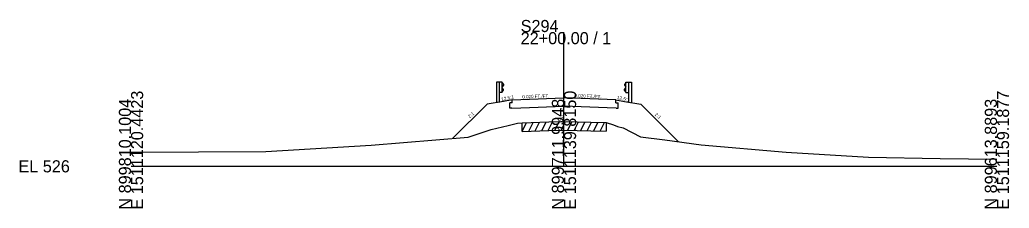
# Model space of a CAD drawing. Extents: x 974 to 2203, y -10 to 19041.
# Drawn here: x 1974.3 to 2202.8, y 3990.3 to 4033.9 of the extents above; entities that cross this region are included whole.
import ezdxf

# ---------------------------------------------------------------- set-up
doc = ezdxf.new("R2010")
doc.units = 0
for name, color, linetype in [('RD_GPK_XS_Cell', 7, 'Continuous'), ('RD_XS_Base', 7, 'Continuous'), ('RD_XS_EarthShd', 7, 'Continuous'), ('RD_XS_ExGround', 7, 'Continuous'), ('RD_XS_ExPaveRet', 7, 'Continuous'), ('RD_XS_GR', 7, 'Continuous'), ('RD_XS_Pave', 7, 'Continuous'), ('RD_XS_TX_Elev_EX', 7, 'Continuous'), ('RD_XS_TX_Slope', 7, 'Continuous')]:
    doc.layers.add(name, color=color, linetype=linetype)

msp = doc.modelspace()

# ---------------------------------------------------------------- linework, layer by layer
at = {"layer": 'RD_GPK_XS_Cell'}
for p, q in [((2100, 4000), (2100, 4031.03)), ((2000, 4000), (2100, 4000)), ((2100, 4000), (2200, 4000))]:
    msp.add_line(p, q, dxfattribs=at)
at = {"layer": 'RD_XS_Base'}
for p, q in [((2088, 4014.7), (2088, 4015.34)), ((2112, 4014.7), (2112, 4015.34)), ((2088, 4014.7), (2087.48, 4014.68)), ((2087.48, 4013.41), (2087.48, 4014.68)), ((2087.98, 4013.43), (2087.48, 4013.41)), ((2087.98, 4013.43), (2090, 4013.51)), ((2090, 4013.51), (2100, 4013.91)), ((2110, 4013.51), (2100, 4013.91)), ((2112.02, 4013.43), (2110, 4013.51)), ((2112, 4014.7), (2112.52, 4014.68)), ((2112.02, 4013.43), (2112.52, 4013.41)), ((2112.52, 4013.41), (2112.52, 4014.68))]:
    msp.add_line(p, q, dxfattribs=at)
at = {"layer": 'RD_XS_EarthShd'}
for p, q in [((2088, 4015.34), (2086, 4015.01)), ((2112, 4015.34), (2114, 4015.01)), ((2074.27, 4006.4), (2082.25, 4014.38)), ((2086, 4015.01), (2082.25, 4014.38)), ((2114, 4015.01), (2117.75, 4014.38)), ((2126.46, 4005.67), (2117.75, 4014.38))]:
    msp.add_line(p, q, dxfattribs=at)
at = {"layer": 'RD_XS_ExGround'}
msp.add_lwpolyline([(2000, 4003.3), (2031.15, 4003.45), (2055.5, 4004.85), (2077.88, 4006.7), (2083.15, 4008.5), (2087.14, 4009.46), (2089.3, 4009.95), (2090.36, 4010.07), (2096.51, 4010.28), (2099.9, 4010.34), (2106.23, 4010.19), (2109.73, 4010.1), (2111.47, 4009.56), (2112.39, 4009.21), (2113.68, 4008.93), (2117.7, 4006.82), (2123.3, 4006.12), (2131.66, 4004.93), (2151.35, 4003.25), (2170.37, 4002.08), (2186.86, 4001.84), (2200, 4001.63)], dxfattribs=at)
at = {"layer": 'RD_XS_ExPaveRet'}
for p, q in [((2090.36, 4008.07), (2091.38, 4010.11)), ((2090.36, 4008.07), (2090.36, 4010.07)), ((2091.86, 4008.12), (2092.88, 4010.16)), ((2093.36, 4008.17), (2094.38, 4010.21)), ((2094.86, 4008.22), (2095.88, 4010.26)), ((2096.36, 4008.27), (2097.37, 4010.3)), ((2097.86, 4008.31), (2098.87, 4010.33)), ((2099.36, 4008.33), (2100.36, 4010.33)), ((2100.86, 4008.32), (2101.85, 4010.3)), ((2102.36, 4008.29), (2103.35, 4010.26)), ((2103.86, 4008.25), (2104.85, 4010.23)), ((2105.36, 4008.21), (2106.35, 4010.19)), ((2106.86, 4008.18), (2107.85, 4010.15)), ((2108.36, 4008.14), (2109.35, 4010.11)), ((2109.73, 4010.1), (2109.73, 4008.1)), ((2090.36, 4008.07), (2096.51, 4008.28)), ((2096.51, 4008.28), (2099.9, 4008.34)), ((2099.9, 4008.34), (2106.23, 4008.19)), ((2106.23, 4008.19), (2109.73, 4008.1))]:
    msp.add_line(p, q, dxfattribs=at)
at = {"layer": 'RD_XS_GR'}
for p, q in [((2084.4, 4019.43), (2084.4, 4014.66)), ((2085.06, 4019.43), (2084.4, 4019.43)), ((2085.06, 4019.43), (2085.06, 4014.77)), ((2085.73, 4019.43), (2085.06, 4019.43)), ((2085.73, 4017.09), (2085.73, 4019.43)), ((2085.73, 4019.28), (2086, 4018.88)), ((2086, 4018.78), (2085.73, 4018.38)), ((2086, 4017.74), (2085.73, 4018.14)), ((2085.73, 4017.24), (2086, 4017.64)), ((2086, 4018.88), (2086, 4018.78)), ((2086, 4017.64), (2086, 4017.74)), ((2114.27, 4019.28), (2114, 4018.88)), ((2114, 4018.88), (2114, 4018.78)), ((2114, 4018.78), (2114.27, 4018.38)), ((2114, 4017.74), (2114.27, 4018.14)), ((2114, 4017.64), (2114, 4017.74)), ((2114.27, 4017.24), (2114, 4017.64)), ((2114.27, 4019.43), (2114.94, 4019.43)), ((2114.27, 4017.09), (2114.27, 4019.43)), ((2114.94, 4019.43), (2114.94, 4014.77)), ((2114.94, 4019.43), (2115.6, 4019.43)), ((2115.6, 4019.43), (2115.6, 4014.66)), ((2085.73, 4017.09), (2085.06, 4017.09)), ((2114.27, 4017.09), (2114.94, 4017.09))]:
    msp.add_line(p, q, dxfattribs=at)
at = {"layer": 'RD_XS_Pave'}
for p, q in [((2088, 4015.34), (2090, 4015.42)), ((2090, 4015.42), (2100, 4015.82)), ((2110, 4015.42), (2100, 4015.82)), ((2112, 4015.34), (2110, 4015.42))]:
    msp.add_line(p, q, dxfattribs=at)

# ---------------------------------------------------------------- texts
at = {"layer": 'RD_GPK_XS_Cell'}
for s, p in [('S294', (2090, 4031.03)), ('22+00.00 / 1', (2090, 4028.23)), ('EL 526', (1974, 3998.6))]:
    msp.add_text(s, height=2.8, dxfattribs=at).set_placement(p)
for s, p in [('N 899810.1004', (2000, 3990)), ('E 1511120.4423', (2002.8, 3990)), ('N 899711.9948', (2100, 3990)), ('E 1511139.8150', (2102.8, 3990)), ('N 899613.8893', (2200, 3990)), ('E 1511159.1877', (2202.8, 3990))]:
    msp.add_text(s, height=2.8, rotation=90, dxfattribs=at).set_placement(p)
at = {"layer": 'RD_XS_TX_Elev_EX'}
msp.add_text('531.17', height=0.75, rotation=90, dxfattribs=at).set_placement((2100, 4010.34))
at = {"layer": 'RD_XS_TX_Slope'}
for s, height, rotation, p in [('12.5:1', 0.778, 12.7511, (2085.61, 4015.09)), ('0.020 FT./FT.', 0.7518, 2.396, (2090.38, 4015.68)), ('0.020 FT./FT.', 0.7518, 357.604, (2102.4, 4015.98)), ('12.5:1', 0.778, 347.2489, (2112.17, 4015.59)), ('2:1', 0.778, 40.6589, (2078.23, 4011.1)), ('2:1', 0.778, 319.3411, (2120.92, 4011.84))]:
    msp.add_text(s, height=height, rotation=rotation, dxfattribs=at).set_placement(p)

doc.saveas('drawing.dxf')
